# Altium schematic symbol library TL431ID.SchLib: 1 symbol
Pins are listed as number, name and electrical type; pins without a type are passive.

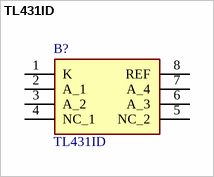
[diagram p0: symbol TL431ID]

## TL431ID
designator B?
2% Accuracy Adjustable Precision Shunt Regulator; Manufacturer_Name: Texas Instruments; Geometry.Height: 1.75mm
footprint SOIC127P600X175-8N
pins: 1 K, 2 A_1, 3 A_2, 4 NC_1, 5 NC_2, 6 A_3, 7 A_4, 8 REF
